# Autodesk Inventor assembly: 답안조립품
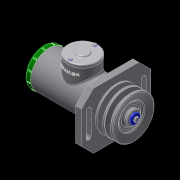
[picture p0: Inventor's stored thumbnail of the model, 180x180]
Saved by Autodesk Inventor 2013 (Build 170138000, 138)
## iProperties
Created: 2017-10
Part Number: 답안조립품
Document SubType Name: Assembly
Designer: Administrator
Author: Administrator
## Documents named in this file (20)
- C:\Users\Administrator\Desktop\471008V1007\답안조립품.iam
- C:\Users\Administrator\Desktop\471008V1007\본체.ipt
- C:\Users\Administrator\Desktop\471008V1007\사이드 커버.ipt
- 사이드 커버.ipt
- C:\Users\Administrator\Desktop\471008V1007\축.ipt
- C:\Users\Administrator\Desktop\471008V1007\멈춤링 15 x 1.ipt
- C:\Users\Administrator\Desktop\471008V1007\멈춤링 35x1.6.ipt
- C:\Users\Administrator\Desktop\471008V1007\베어링 15 x 35 x 11.ipt
- C:\Users\Administrator\Desktop\471008V1007\부시1.ipt
- C:\Users\Administrator\Desktop\471008V1007\부시2.ipt
- C:\Users\Administrator\Desktop\471008V1007\와셔 10x21.ipt
- C:\Users\Administrator\Desktop\471008V1007\너트 M10.ipt
- C:\Users\Administrator\Desktop\471008V1007\오일 실 15 25 7.ipt
- C:\Users\Administrator\Desktop\471008V1007\키 4 x 4 x 18.ipt
- C:\Users\Administrator\Desktop\471008V1007\V-벨트풀리.ipt
- C:\Users\Administrator\Desktop\471008V1007\와셔 4x16.ipt
- C:\Users\Administrator\Desktop\471008V1007\볼트 M4 x 10.ipt
- C:\Users\Administrator\Desktop\471008V1007\탑 커버.ipt
- C:\Users\Administrator\Desktop\471008V1007\와셔 3x6.ipt
- C:\Users\Administrator\Desktop\471008V1007\십자볼트 M3 x 10.ipt
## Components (2 placed, 2 different names)
1. V-벨트풀리:1 — 각도:2
2. ISO 4017 M4 x 10:1
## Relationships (1: Angle 1)
- 각도:2 [Angle]: V-벨트풀리:1
